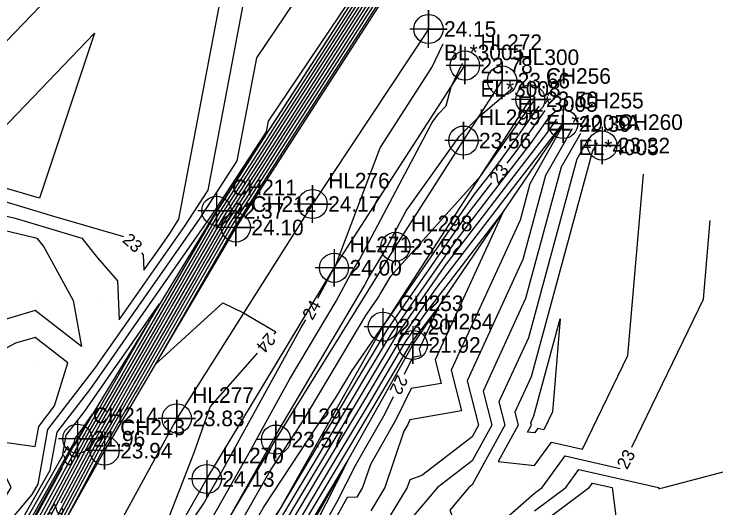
# Model space of a CAD drawing. Extents: x 2531902 to 2533249, y 715219 to 716099.
# Drawn here: x 2532966.6 to 2533079.1, y 715886.7 to 715966 of the extents above; entities that cross this region are included whole.
import ezdxf

# ---------------------------------------------------------------- set-up
doc = ezdxf.new("R2010")
doc.units = 0
for name, color, linetype in [('DTM Contours Major', 7, 'Continuous'), ('DTM Contours Major Text', 7, 'Continuous'), ('DTM Contours Minor', 7, 'Continuous'), ('Exist DTM Breakline', 7, 'Continuous'), ('Exist DTM Breakline Cogo Comment', 7, 'Continuous'), ('Exist DTM Breakline Cogo Elevation', 7, 'Continuous'), ('Exist DTM Breakline Cogo Number', 7, 'Continuous'), ('Exist DTM Breakline Cogo Point CELL', 7, 'Continuous'), ('Exist DTM Crownline', 7, 'Continuous'), ('Exist DTM Crownline Cogo Comment', 7, 'Continuous'), ('Exist DTM Crownline Cogo Elevation', 7, 'Continuous'), ('Exist DTM Crownline Cogo Number', 7, 'Continuous'), ('Exist DTM Crownline Cogo Point CELL', 7, 'Continuous'), ('Exist DTM QL2 LIDAR Elevation Point', 7, 'Continuous'), ('Exist DTM Regular Point CELL', 7, 'Continuous'), ('Exist DTM Regular Point Cogo Elevation', 7, 'Continuous'), ('Exist DTM Regular Point Cogo Number', 7, 'Continuous'), ('Exist Roads Soil', 7, 'Continuous'), ('Exist Roads Soil Cogo Comment', 7, 'Continuous'), ('Exist Roads Soil Cogo Elevation', 7, 'Continuous'), ('Exist Roads Soil Cogo Number', 7, 'Continuous'), ('Exist Roads Soil Cogo Point CELL', 7, 'Continuous')]:
    doc.layers.add(name, color=color, linetype=linetype)

msp = doc.modelspace()

# ---------------------------------------------------------------- linework, layer by layer
at = {"layer": 'DTM Contours Major'}
for points in [[(2532994.27, 715991.68), (2532965.29, 715961.47), (2532951.58, 715944.21), (2532956.58, 715940), (2532960, 715937.18), (2532963.69, 715936.31), (2532972.94, 715933.53), (2532984.14, 715930.25)], [(2532987.02, 715927.65), (2532987.31, 715927.31), (2532987.42, 715924.85), (2532989.19, 715927.38), (2532991.54, 715930.75), (2532993.03, 715933.04), (2533001.76, 715979.28), (2533005.16, 715984.34)], [(2533025.67, 715973.09), (2533019.98, 715964.21), (2533009.47, 715947.89), (2533005.61, 715941.87), (2533000.16, 715933.42), (2532991.95, 715919.23), (2532985.12, 715907.36), (2532982, 715901.96), (2532979.05, 715896.82), (2532974.08, 715887.48)], [(2533028.66, 715973.55), (2533013.61, 715950.04), (2533012.51, 715948.33), (2533002.46, 715932.64), (2533001.96, 715931.87), (2533001.21, 715930.58), (2532989.22, 715909.73), (2533000.04, 715919.65), (2533003.39, 715918.04), (2533008.57, 715915), (2533008.21, 715914.58)], [(2533015.29, 715920.39), (2533017.92, 715925.23), (2533017.95, 715925.28), (2533018.24, 715925.82), (2533025.27, 715944.47), (2533033.55, 715957.38), (2533035.38, 715961.16)], [(2533045.6, 715942.05), (2533047.03, 715943.91), (2533051.69, 715950.48)], [(2533058.68, 715946.05), (2533056.8, 715942.7), (2533049.02, 715914.04), (2533044.29, 715903.77), (2533045.26, 715900), (2533040, 715890.42), (2533039.46, 715890), (2533036.4, 715886.4), (2533037.44, 715883.72), (2533042.53, 715882.53), (2533050, 715889.09), (2533051.22, 715890), (2533054.9, 715895.1), (2533063.73, 715893.08)], [(2532990.66, 715853.91), (2533001.12, 715872.99), (2533001.28, 715873.26), (2533004.52, 715879.18), (2533005.5, 715880.89), (2533009.27, 715886.63), (2533020.43, 715905.29), (2533021.07, 715906.38), (2533026.44, 715915.35), (2533038.85, 715933.27), (2533043.17, 715938.88)], [(2533065.57, 715896.48), (2533077.05, 715920.21), (2533078.13, 715932.84)], [(2532990.66, 715843.93), (2532991.05, 715844.67), (2533001.18, 715862.95), (2533005.42, 715870.96), (2533007.93, 715875.44), (2533008.78, 715877.06), (2533022.04, 715899.35), (2533024.1, 715902.79), (2533029.81, 715912.39), (2533030.2, 715913.06), (2533031.12, 715914.38), (2533034.62, 715918.94), (2533031.52, 715912.2), (2533031.8, 715911.11), (2533030.43, 715910.87), (2533029.09, 715908.14)], [(2533005.57, 715911.57), (2532998.05, 715902.99), (2532995.41, 715895.57), (2532989.73, 715880.96), (2532986.95, 715876.24), (2532986.54, 715875.54), (2532985.74, 715870.71), (2532989.49, 715876.27), (2532989.64, 715876.51), (2532996.95, 715887.38), (2533000.03, 715892.83), (2533012.63, 715915.67), (2533013.36, 715916.89)], [(2533027.33, 715904.54), (2533025.99, 715901.81), (2533021.38, 715893.7), (2533018.34, 715887.73), (2533012.52, 715877.21), (2533013.22, 715874.98), (2533009.99, 715871.53), (2533009.32, 715870.03), (2533008.58, 715864.55), (2533001.66, 715851.66), (2533001.19, 715850), (2533000, 715844.5), (2532999.51, 715840.25), (2532999.38, 715839.86), (2532998.95, 715830.86), (2532998.16, 715830), (2533000, 715828.69), (2533002.98, 715827.02), (2533003.47, 715830), (2533002.3, 715837.7), (2533002.1, 715839.01)], [(2532934.47, 715853.45), (2532938.07, 715850), (2532937.98, 715842.02), (2532937.6, 715840), (2532938.93, 715839.38), (2532939.96, 715838.85), (2532940.96, 715840.37), (2532940.92, 715848.37), (2532948.85, 715856.1), (2532954.16, 715863.18), (2532956.69, 715868.37), (2532958.45, 715871.12), (2532961.86, 715872.75), (2532963.44, 715874.61), (2532976.31, 715897.32), (2532976.42, 715897.93), (2532976.96, 715898.64), (2532979.15, 715901.78), (2532976.97, 715898), (2532976.84, 715897.78), (2532976.47, 715897.08), (2532976.23, 715896.64)], [(2532974.31, 715893.14), (2532962.46, 715871.48), (2532962.28, 715871.14), (2532960.23, 715867.39), (2532948.23, 715846.19), (2532945.52, 715841.22), (2532941.98, 715834.93), (2532940.91, 715832.96), (2532936.11, 715824.03), (2532926.97, 715806.39), (2532926.41, 715805.36)]]:
    msp.add_lwpolyline(points, dxfattribs=at)
at = {"layer": 'DTM Contours Minor'}
for points in [[(2532986.69, 715997.14), (2532969.72, 715979.44), (2532944.52, 715947.74), (2532953.71, 715940), (2532960, 715934.82), (2532966.79, 715933.21), (2532977.49, 715930), (2532980, 715926.86), (2532983.16, 715923.16), (2532983.45, 715916.91), (2532987.93, 715923.34), (2532993.91, 715931.9), (2532997.7, 715937.72), (2533003.63, 715969.12), (2533011.32, 715980.55)], [(2532960.47, 715878.18), (2532969.52, 715888.87), (2532970.46, 715890.54), (2532972.03, 715899.34), (2532979.87, 715909.53), (2532980.16, 715909.94), (2532986.68, 715919.3), (2532996.29, 715933.06), (2533002.37, 715942.4), (2533005.49, 715958.95), (2533017.47, 715976.75)], [(2533023.88, 715972.82), (2533023.81, 715972.71), (2533007.64, 715947.63), (2533007.5, 715947.41), (2532999.08, 715934.34), (2532986.39, 715912.42), (2532984.01, 715908.28), (2532978.98, 715899.59), (2532977.72, 715897.4), (2532974, 715890.4), (2532963.42, 715871.07)], [(2533024.47, 715972.91), (2533022.53, 715969.88), (2533008.25, 715947.72), (2533006.87, 715945.56), (2532999.44, 715934.03), (2532988.24, 715914.69), (2532984.38, 715907.97), (2532979.99, 715900.38), (2532978.16, 715897.21), (2532972.77, 715887.07), (2532963.9, 715870.86)], [(2533027.47, 715973.37), (2533016.16, 715955.71), (2533011.29, 715948.16), (2533003.72, 715936.33), (2533001.24, 715932.49), (2532997.51, 715926.04), (2532986.23, 715906.44), (2532985.02, 715904.34), (2532980.37, 715896.25), (2532966.6, 715870.38)], [(2532967.49, 715884.12), (2532972.41, 715892.8), (2532973.49, 715898.87), (2532978.9, 715905.9), (2532981.41, 715909.49), (2532985.43, 715915.26), (2532998.66, 715934.21), (2533007.04, 715947.08), (2533007.36, 715948.78), (2533023.63, 715972.96)], [(2533026.87, 715973.28), (2533017.43, 715958.54), (2533010.68, 715948.07), (2533004.35, 715938.18), (2533000.88, 715932.8), (2532995.66, 715923.77), (2532985.86, 715906.75), (2532984.01, 715903.55), (2532979.93, 715896.44), (2532967.84, 715873.72)], [(2533026.27, 715973.19), (2533018.71, 715961.38), (2533010.08, 715947.98), (2533004.98, 715940.02), (2533000.52, 715933.11), (2532993.8, 715921.5), (2532985.49, 715907.05), (2532983.01, 715902.76), (2532979.49, 715896.63), (2532969.07, 715877.05)], [(2533025.07, 715973), (2533021.26, 715967.04), (2533008.86, 715947.8), (2533006.24, 715943.72), (2532999.8, 715933.72), (2532990.1, 715916.96), (2532984.75, 715907.67), (2532980.99, 715901.17), (2532978.6, 715897.02), (2532971.54, 715883.73)], [(2533028.07, 715973.46), (2533014.88, 715952.88), (2533011.9, 715948.24), (2533003.09, 715934.49), (2533001.6, 715932.18), (2532999.36, 715928.31), (2532986.61, 715906.13), (2532986.03, 715905.13), (2532980.81, 715896.06), (2532974.41, 715884.04)], [(2532960, 715939.54), (2532959.44, 715940), (2532958.63, 715940.68), (2532960.86, 715943.49), (2532979.49, 715962.91), (2532970.67, 715936.44), (2532962.1, 715938.95), (2532960.6, 715939.4), (2532960, 715939.54)], [(2532996.1, 715881.12), (2533004, 715895.09), (2533010.75, 715907.31), (2533018.22, 715919.91), (2533020.64, 715924.38), (2533022, 715926.66), (2533033.59, 715948.54), (2533034.61, 715949.96), (2533035.86, 715951.22), (2533036.63, 715954.28), (2533038.47, 715958.06)], [(2533000.47, 715884.08), (2533007.98, 715897.35), (2533008.86, 715898.94), (2533022.71, 715922.32), (2533023.36, 715923.52), (2533026.04, 715928.05), (2533029.41, 715934.41), (2533037.96, 715946.34), (2533041.03, 715949.42), (2533046.51, 715954.13)], [(2532998.59, 715876.78), (2533007.66, 715892.68), (2533012.95, 715900.73), (2533022.96, 715917.61), (2533024.87, 715920.36), (2533026.97, 715923.92), (2533041.37, 715939.99), (2533041.95, 715940.82), (2533042.05, 715940.96), (2533042.11, 715941.04), (2533049.81, 715951.9)], [(2533001.56, 715877.98), (2533006.58, 715886.79), (2533018.1, 715904.32), (2533020.76, 715908.8), (2533025.68, 715915.89), (2533025.73, 715915.96), (2533026, 715916.27), (2533040.4, 715937.05), (2533042.97, 715940.39), (2533044.57, 715942.48), (2533050.75, 715951.19)], [(2533007.92, 715882.65), (2533021.16, 715904.79), (2533022.82, 715907.58), (2533027.19, 715914.89), (2533037.31, 715929.49), (2533044.81, 715939.26), (2533049.5, 715945.35), (2533052.63, 715949.78)], [(2533006.55, 715878.58), (2533011.45, 715886.82), (2533021.9, 715904.29), (2533024.57, 715908.78), (2533027.94, 715914.43), (2533035.76, 715925.71), (2533045.73, 715938.69), (2533051.96, 715946.79), (2533053.57, 715949.07)], [(2533007.29, 715878.07), (2533014.98, 715891), (2533022.63, 715903.79), (2533026.31, 715909.99), (2533028.7, 715913.97), (2533034.21, 715921.94), (2533046.65, 715938.12), (2533054.42, 715948.22), (2533054.51, 715948.36)], [(2533054.66, 715948.27), (2533049.27, 715938.71), (2533047.69, 715932.89), (2533036.63, 715908.83), (2533038.31, 715902.29), (2533030.03, 715900.87), (2533029.68, 715900.14), (2533029.06, 715899.06), (2533026.02, 715890), (2533023.75, 715886.25)], [(2533056, 715947.53), (2533051.78, 715940.04), (2533048.13, 715926.6), (2533039.18, 715907.14), (2533041.02, 715900), (2533040, 715898.14), (2533031.96, 715891.96), (2533030, 715891.25), (2533029.58, 715890), (2533025.98, 715884.02)], [(2533057.34, 715946.79), (2533054.29, 715941.37), (2533048.57, 715920.32), (2533041.74, 715905.45), (2533043.14, 715900), (2533040, 715894.28), (2533034.43, 715890), (2533030, 715884.78)], [(2533060.03, 715945.31), (2533059.31, 715944.03), (2533049.46, 715907.76), (2533046.85, 715902.08), (2533047.38, 715900), (2533044.19, 715894.19), (2533050, 715893.54), (2533052.71, 715897.29), (2533057.69, 715896.16), (2533064.95, 715911.17), (2533067.45, 715940.27)], [(2533008.04, 715877.57), (2533018.51, 715895.17), (2533023.37, 715903.29), (2533028.06, 715911.19), (2533029.45, 715913.51), (2533032.67, 715918.16), (2533044.93, 715934.12), (2533034.08, 715910.51), (2533035.06, 715906.7), (2533030.23, 715905.87), (2533027.84, 715900.98), (2533023.69, 715893.69), (2533022.45, 715890), (2533021.53, 715888.47), (2533020, 715888.4), (2533014.14, 715877.82)], [(2532960, 715932.45), (2532969.88, 715930.12), (2532970.28, 715930), (2532971.38, 715928.62), (2532976.06, 715920), (2532977.39, 715912.61), (2532970, 715918.41), (2532963.51, 715916.49)], [(2532965.46, 715879.36), (2532974.36, 715895.06), (2532974.96, 715898.4), (2532977.93, 715902.27), (2532982.66, 715909.04), (2532984.17, 715911.21), (2532989.92, 715919.45), (2532984.54, 715910.14), (2532983.64, 715908.59), (2532977.98, 715898.79), (2532977.28, 715897.59), (2532975.24, 715893.74), (2532962.94, 715871.27)], [(2533049.4, 715900.4), (2533049.9, 715901.48), (2533054.13, 715917.08), (2533052.85, 715902.13), (2533051.47, 715899.27), (2533050.52, 715899.48), (2533050, 715898.77), (2533048.89, 715898.89), (2533049.5, 715900), (2533049.4, 715900.4)], [(2532960, 715879.99), (2532960.05, 715880.05), (2532966.15, 715890), (2532962.35, 715897.65), (2532970, 715896.61), (2532970.57, 715899.82), (2532973.1, 715903.1), (2532975.2, 715910), (2532970, 715914.08), (2532966.85, 715913.15), (2532960.92, 715910), (2532960, 715907.1), (2532957.22, 715902.78), (2532958.01, 715900), (2532954.36, 715895.64), (2532956.64, 715890), (2532959.98, 715880.02), (2532959.99, 715880), (2532959.99, 715879.99), (2532960, 715879.99)], [(2533050, 715886.27), (2533054.99, 715890), (2533057.09, 715892.91), (2533069.84, 715890), (2533069.86, 715889.86), (2533070, 715889.83), (2533070.73, 715890), (2533094.65, 715896.3), (2533114.87, 715902.88), (2533118.6, 715904.23)], [(2533009.53, 715876.55), (2533020.03, 715894.21), (2533013.03, 715880.46)], [(2533050, 715883.45), (2533058.77, 715890), (2533059.28, 715890.72), (2533062.43, 715890), (2533063.31, 715883.31)]]:
    msp.add_lwpolyline(points, dxfattribs=at)
at = {"layer": 'Exist DTM Breakline'}
for points in [[(2533023.85, 715972.82), (2532999.03, 715934.39), (2532976.75, 715897.83), (2532959.92, 715867.59), (2532939.77, 715833.59), (2532921.01, 715799.34), (2532899.77, 715758.66), (2532880.47, 715715.6), (2532864.43, 715683.53), (2532849.72, 715661.42)], [(2533029.09, 715973.62), (2533002.14, 715931.72), (2532981.11, 715895.92), (2532963.78, 715865.17), (2532944.31, 715831.08), (2532924.28, 715797.5), (2532904.49, 715756.17), (2532883.85, 715713.92), (2532865.56, 715669.75), (2532864.57, 715660.11), (2532866.15, 715657.26), (2532867.93, 715656.56)], [(2532886.28, 715647.71), (2532887.83, 715646.82), (2532890.15, 715647.1), (2532894.46, 715651.17), (2532901.38, 715665.17), (2532911.1, 715687.19), (2532923.2, 715712.64), (2532936.34, 715739.9), (2532954.94, 715777.13), (2532972.65, 715814.18), (2532988.13, 715846.38), (2533005.24, 715879.47), (2533025.7, 715915.8), (2533049.32, 715952.27)], [(2532892.99, 715644.66), (2532898.12, 715649.31), (2532907.03, 715662.8), (2532916.8, 715684.71), (2532927.54, 715709.35), (2532941.28, 715737.3), (2532958.47, 715775.09), (2532977.03, 715811), (2532993.18, 715843.42), (2533009.96, 715876.26), (2533030.5, 715912.87), (2533054.58, 715948.32)]]:
    msp.add_lwpolyline(points, dxfattribs=at)
at = {"layer": 'Exist DTM Breakline Cogo Point CELL'}
for points in [[(2533049.32, 715955.27), (2533049.32, 715949.27), (2533049.32, 715952.27), (2533052.32, 715952.27), (2533046.32, 715952.27)], [(2533054.58, 715951.32), (2533054.58, 715945.32), (2533054.58, 715948.32), (2533057.58, 715948.32), (2533051.58, 715948.32)], [(2532999.03, 715937.39), (2532999.03, 715931.39), (2532999.03, 715934.39), (2533002.03, 715934.39), (2532996.03, 715934.39)], [(2533002.14, 715934.72), (2533002.14, 715928.72), (2533002.14, 715931.72), (2533005.14, 715931.72), (2532999.14, 715931.72)], [(2533025.7, 715918.8), (2533025.7, 715912.8), (2533025.7, 715915.8), (2533028.7, 715915.8), (2533022.7, 715915.8)], [(2533030.5, 715915.87), (2533030.5, 715909.87), (2533030.5, 715912.87), (2533033.5, 715912.87), (2533027.5, 715912.87)], [(2532976.75, 715900.83), (2532976.75, 715894.83), (2532976.75, 715897.83), (2532979.75, 715897.83), (2532973.75, 715897.83)], [(2532981.11, 715898.92), (2532981.11, 715892.92), (2532981.11, 715895.92), (2532984.11, 715895.92), (2532978.11, 715895.92)]]:
    msp.add_lwpolyline(points, dxfattribs=at)
for centre in [(2533049.32, 715952.27), (2533054.58, 715948.32), (2532999.03, 715934.39), (2533002.14, 715931.72), (2533025.7, 715915.8), (2533030.5, 715912.87), (2532976.75, 715897.83), (2532981.11, 715895.92)]:
    msp.add_circle(centre, 2.34, dxfattribs=at)
at = {"layer": 'Exist DTM Crownline'}
msp.add_lwpolyline([(2532876.57, 715652.01), (2532884.04, 715667.73), (2532897.27, 715696.35), (2532912.05, 715728.69), (2532925.33, 715755.88), (2532939.89, 715784.74), (2532958.95, 715822.25), (2532974.27, 715850.52), (2532997.48, 715891.38), (2533017.87, 715925.25), (2533038.84, 715957.69)], dxfattribs=at)
at = {"layer": 'Exist DTM Crownline Cogo Point CELL'}
for points in [[(2533038.84, 715960.69), (2533038.84, 715954.69), (2533038.84, 715957.69), (2533041.84, 715957.69), (2533035.84, 715957.69)], [(2533017.87, 715928.25), (2533017.87, 715922.25), (2533017.87, 715925.25), (2533020.87, 715925.25), (2533014.87, 715925.25)], [(2532997.48, 715894.38), (2532997.48, 715888.38), (2532997.48, 715891.38), (2533000.48, 715891.38), (2532994.48, 715891.38)]]:
    msp.add_lwpolyline(points, dxfattribs=at)
for centre in [(2533038.84, 715957.69), (2533017.87, 715925.25), (2532997.48, 715891.38)]:
    msp.add_circle(centre, 2.34, dxfattribs=at)
at = {"layer": 'Exist DTM QL2 LIDAR Elevation Point'}
for p, q in [((2532970, 715930), (2532970, 715930)), ((2532980, 715930), (2532980, 715930)), ((2532990, 715930), (2532990, 715930)), ((2532970, 715920), (2532970, 715920)), ((2532980, 715920), (2532980, 715920)), ((2532970, 715910), (2532970, 715910)), ((2532980, 715910), (2532980, 715910)), ((2532970, 715900), (2532970, 715900)), ((2533030, 715900), (2533030, 715900)), ((2533040, 715900), (2533040, 715900)), ((2533050, 715900), (2533050, 715900)), ((2532970, 715890), (2532970, 715890)), ((2533020, 715890), (2533020, 715890)), ((2533030, 715890), (2533030, 715890)), ((2533040, 715890), (2533040, 715890)), ((2533050, 715890), (2533050, 715890)), ((2533060, 715890), (2533060, 715890)), ((2533070, 715890), (2533070, 715890))]:
    msp.add_line(p, q, dxfattribs=at)
at = {"layer": 'Exist DTM Regular Point CELL'}
msp.add_lwpolyline([(2533060.85, 715947.86), (2533060.85, 715941.86), (2533060.85, 715944.86), (2533063.85, 715944.86), (2533057.85, 715944.86)], dxfattribs=at)
msp.add_circle((2533060.85, 715944.86), 2.34, dxfattribs=at)
at = {"layer": 'Exist Roads Soil'}
for points in [[(2533033, 715963.55), (2533014.44, 715935.48), (2532992.67, 715901.09), (2532976.47, 715871.31), (2532962.05, 715845.13), (2532943.27, 715807.99), (2532921.98, 715764.36), (2532902.69, 715724.28), (2532889.07, 715694.2), (2532879.25, 715673.17), (2532870.65, 715655.41), (2532876.57, 715652.01), (2532882.44, 715649.38)], [(2532882.44, 715649.38), (2532884.45, 715653.58), (2532893.83, 715673.24), (2532904.08, 715695.07), (2532909.89, 715707.28), (2532923.66, 715737.55), (2532935.37, 715761.59), (2532947.64, 715787.12), (2532960.72, 715812.47), (2532979.3, 715846.3), (2532995.34, 715875.46), (2533008.57, 715897.69), (2533027.7, 715928.62), (2533038.6, 715945.65), (2533044.8, 715955.28)]]:
    msp.add_lwpolyline(points, dxfattribs=at)
at = {"layer": 'Exist Roads Soil Cogo Point CELL'}
for points in [[(2533033, 715960.55), (2533033, 715966.55), (2533033, 715963.55), (2533036, 715963.55), (2533030, 715963.55)], [(2533044.8, 715952.28), (2533044.8, 715958.28), (2533044.8, 715955.28), (2533047.8, 715955.28), (2533041.8, 715955.28)], [(2533038.6, 715942.65), (2533038.6, 715948.65), (2533038.6, 715945.65), (2533041.6, 715945.65), (2533035.6, 715945.65)], [(2533014.44, 715932.48), (2533014.44, 715938.48), (2533014.44, 715935.48), (2533017.44, 715935.48), (2533011.44, 715935.48)], [(2533027.7, 715925.62), (2533027.7, 715931.62), (2533027.7, 715928.62), (2533030.7, 715928.62), (2533024.7, 715928.62)], [(2532992.67, 715898.09), (2532992.67, 715904.09), (2532992.67, 715901.09), (2532995.67, 715901.09), (2532989.67, 715901.09)], [(2533008.57, 715894.69), (2533008.57, 715900.69), (2533008.57, 715897.69), (2533011.57, 715897.69), (2533005.57, 715897.69)]]:
    msp.add_lwpolyline(points, dxfattribs=at)
for centre in [(2533033, 715963.55), (2533044.8, 715955.28), (2533038.6, 715945.65), (2533014.44, 715935.48), (2533027.7, 715928.62), (2532992.67, 715901.09), (2533008.57, 715897.69)]:
    msp.add_circle(centre, 2.34, dxfattribs=at)

# ---------------------------------------------------------------- texts
at = {"layer": 'DTM Contours Major Text'}
for s, rotation, p in [('23', 52.457, (2533044.18, 715938.56)), ('23', 317.8115, (2532983.84, 715929.52)), ('24', 61.1, (2533014.42, 715916.72)), ('24', 228.7491, (2533007.21, 715914.96)), ('22', 243.9545, (2533028.03, 715908.24)), ('22', 241.3093, (2532975.18, 715896.8)), ('23', 61.5649, (2533064.81, 715892.77)), ('23', 241.9877, (2532973.02, 715887.63))]:
    msp.add_text(s, height=2, rotation=rotation, dxfattribs=at).set_placement(p)
at = {"layer": 'Exist DTM Breakline Cogo Comment'}
for s, p in [('EL*4005A', (2533051.82, 715947.27)), ('EL*4005', (2533057.08, 715943.32))]:
    msp.add_text(s, height=2.5, dxfattribs=at).set_placement(p)
at = {"layer": 'Exist DTM Breakline Cogo Elevation'}
for s, p in [('23.50', (2533051.82, 715951.02)), ('22.39', (2533057.08, 715947.07)), ('22.37', (2533001.53, 715933.14)), ('24.10', (2533004.64, 715930.47)), ('23.20', (2533028.2, 715914.55)), ('21.92', (2533033, 715911.62)), ('21.96', (2532979.25, 715896.58)), ('23.94', (2532983.61, 715894.67))]:
    msp.add_text(s, height=2.5, dxfattribs=at).set_placement(p)
at = {"layer": 'Exist DTM Breakline Cogo Number'}
for s, p in [('CH256', (2533051.82, 715954.77)), ('CH255', (2533057.08, 715950.82)), ('CH211', (2533001.53, 715936.89)), ('CH212', (2533004.64, 715934.22)), ('CH253', (2533028.2, 715918.3)), ('CH254', (2533033, 715915.37)), ('CH214', (2532979.25, 715900.33)), ('CH213', (2532983.61, 715898.42))]:
    msp.add_text(s, height=2.5, dxfattribs=at).set_placement(p)
at = {"layer": 'Exist DTM Crownline Cogo Comment'}
msp.add_text('EL*3008', height=2.5, dxfattribs=at).set_placement((2533041.34, 715952.69))
at = {"layer": 'Exist DTM Crownline Cogo Elevation'}
for s, p in [('23.78', (2533041.34, 715956.44)), ('24.00', (2533020.37, 715924)), ('24.13', (2532999.98, 715890.13))]:
    msp.add_text(s, height=2.5, dxfattribs=at).set_placement(p)
at = {"layer": 'Exist DTM Crownline Cogo Number'}
for s, p in [('HL272', (2533041.34, 715960.19)), ('HL271', (2533020.37, 715927.75)), ('HL270', (2532999.98, 715893.88))]:
    msp.add_text(s, height=2.5, dxfattribs=at).set_placement(p)
at = {"layer": 'Exist DTM Regular Point Cogo Elevation'}
msp.add_text('23.32', height=2.5, dxfattribs=at).set_placement((2533063.35, 715943.61))
at = {"layer": 'Exist DTM Regular Point Cogo Number'}
msp.add_text('CH260', height=2.5, dxfattribs=at).set_placement((2533063.35, 715947.36))
at = {"layer": 'Exist Roads Soil Cogo Comment'}
for s, p in [('BL*3005', (2533035.5, 715958.55)), ('EL*3005', (2533047.3, 715950.28))]:
    msp.add_text(s, height=2.5, dxfattribs=at).set_placement(p)
at = {"layer": 'Exist Roads Soil Cogo Elevation'}
for s, p in [('24.15', (2533035.5, 715962.3)), ('23.66', (2533047.3, 715954.03)), ('23.56', (2533041.1, 715944.4)), ('24.17', (2533016.94, 715934.23)), ('23.52', (2533030.2, 715927.37)), ('23.83', (2532995.17, 715899.84)), ('23.57', (2533011.07, 715896.44))]:
    msp.add_text(s, height=2.5, dxfattribs=at).set_placement(p)
at = {"layer": 'Exist Roads Soil Cogo Number'}
for s, p in [('HL300', (2533047.3, 715957.78)), ('HL299', (2533041.1, 715948.15)), ('HL276', (2533016.94, 715937.98)), ('HL298', (2533030.2, 715931.12)), ('HL277', (2532995.17, 715903.59)), ('HL297', (2533011.07, 715900.19))]:
    msp.add_text(s, height=2.5, dxfattribs=at).set_placement(p)

doc.saveas('drawing.dxf')
